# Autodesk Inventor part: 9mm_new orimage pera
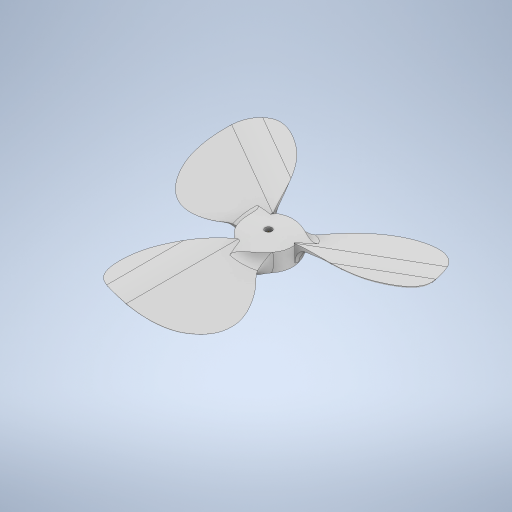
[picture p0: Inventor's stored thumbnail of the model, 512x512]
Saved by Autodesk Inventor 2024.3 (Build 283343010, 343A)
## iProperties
Created: 2025-07
Part Number: 9mm_new orimage pera
Material: 一般
Document SubType Name: Modeling
Designer: node49i5
Density: 1 g/cm^3
Appearance: 既定
Author: node49i5
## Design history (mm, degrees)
sketch "スケッチ1"
  geometry: L1 (-30.949, 12.329)-(37.93, -12.741); L2 (37.93, -12.741)-(37.246, -14.62); L3 (37.246, -14.62)-(-31.302, 10.329); L4 (-37.93, 12.741)-(-37.246, 14.62); L5 (-37.246, 14.62)-(37.246, -14.62); L6 (37.93, -12.741)-(-37.93, 12.741); L7 (-37.246, 14.62)-(36.054, 14.62); L8 (-44.983, 12.741)-(-87.93, 12.741); L9 (-87.93, 12.741)-(-87.93, 14.741); L10 (-87.93, 14.741)-(-44.63, 14.741); L11 (-37.93, 14.741)-(-37.93, 12.741); A1 r 40 centre (-44.63, -25.259) between (-30.949, 12.329) and (-44.63, 14.741); A2 r 40 centre (-44.983, -27.259) between (-31.302, 10.329) and (-44.983, 12.741); 7 further points
  constraints: 22 end point, 8 point on line, 4 parallel, 4 point on circle, 4 tangent, 2 centre point, 2 horizontal, 2 midpoint, 2 perpendicular, 1 equal length, 1 equal radius
  dimensions: "d0" = 80 distance of L4.end L1.end; "d1" = 20 deg angle of L1 L7; "d2" = 2 distance of L1.end L2.end; "d3" = 2 distance of L11.start L4.start; "d4" = 50 distance of L9.end L11.start; "d9" = 40 radius of A1 (derived)
extrude "押し出し1" new body sketch "スケッチ1" distance "d6" = 100; taper "d7" = 0 deg
node "作業平面1"
sketch "スケッチ2"
  geometry: L1 (-37.93, 0)-(30.949, 0) reference; L2 (44.63, 0)-(30.949, 0) reference; L3 (44.63, 0)-(87.93, 0) reference; L4 (30.949, 0)-(30.949, 100) reference; L5 (44.63, 0)-(87.93, 0) reference; L6 (87.93, 0)-(87.93, 100) reference; L7 (44.63, 100)-(87.93, 100) reference; L8 (44.63, 0)-(44.63, 100) reference; L9 (30.949, 0)-(44.63, 0) reference; L10 (44.63, 0)-(44.63, 100) reference; L11 (30.949, 100)-(44.63, 100) reference; L12 (30.949, 0)-(30.949, 100) reference; L13 (-37.93, 0)-(30.949, 0) reference; L14 (30.949, 0)-(30.949, 100) reference; L15 (-37.93, 100)-(30.949, 100) reference; L16 (-37.93, 0)-(-37.93, 100) reference; 38 further points
  constraints: 21 other
  dimensions: "d10" = 9.94761 horizontal distance of point (20.676, 0) point (30.624, -1.041); "d11" = 1.04092 vertical distance of point (20.676, 0) point (30.624, -1.041); "d12" = 0 distance from line of L1 point (20.676, 0); "d45" = 11.68753 distance of point (52.709, 40.854) point (53.63, 52.505); "d46" = 7.46898 distance of point (53.63, 52.505) point (52.49, 59.886); "d47" = 19.54185 distance of point (50.664, 33.189) point (53.63, 52.505); "d48" = 12.36264 distance of point (53.63, 52.505) point (50.15, 64.367); "d49" = 29.23719 distance of point (46.769, 24.084) point (53.63, 52.505); "d50" = 16.67901 distance of point (53.63, 52.505) point (46.053, 67.363); "d51" = 41.60846 distance of point (40.339, 13.076) point (53.63, 52.505); "d52" = 22.43867 distance of point (53.63, 52.505) point (38.766, 69.314); "d53" = 58.27878 distance of point (30.624, -1.041) point (53.63, 52.505); "d54" = 30.32407 distance of point (53.63, 52.505) point (28.314, 69.198); "d55" = 61.98945 distance of point (20.676, 0) point (53.63, 52.505); "d56" = 39.24643 distance of point (53.63, 52.505) point (16.7, 65.789); "d57" = 60.90235 distance of point (53.63, 52.505) point (11.699, 8.336); "d58" = 43.39618 distance of point (53.63, 52.505) point (11.48, 62.827); "d59" = 47.01927 distance of point (53.63, 52.505) point (7.089, 59.19); "d60" = 60.66906 distance of point (53.63, 52.505) point (5.993, 14.936); "d61" = 52.6052 distance of point (53.63, 52.505) point (1.057, 50.678); "d62" = 56.29782 distance of point (53.63, 52.505) point (-1.747, 42.366); "d63" = 58.4343 distance of point (53.63, 52.505) point (-2.076, 34.86); "d64" = 19.03382 distance of point (52.709, 40.854) point (52.49, 59.886); "d65" = 7.93234 distance of point (50.664, 33.189) point (52.709, 40.854); "d66" = 23.65264 distance of point (52.709, 40.854) point (50.15, 64.367); "d67" = 17.79037 distance of point (46.769, 24.084) point (52.709, 40.854); "d68" = 27.33244 distance of point (52.709, 40.854) point (46.053, 67.363); "d69" = 30.40715 distance of point (40.339, 13.076) point (52.709, 40.854); "d70" = 31.69225 distance of point (52.709, 40.854) point (38.766, 69.314); "d71" = 47.35906 distance of point (30.624, -1.041) point (52.709, 40.854); "d72" = 37.39633 distance of point (52.709, 40.854) point (28.314, 69.198); "d73" = 43.79921 distance of point (52.709, 40.854) point (16.7, 65.789); "d74" = 52.33729 distance of point (52.709, 40.854) point (11.699, 8.336); "d75" = 46.71921 distance of point (52.709, 40.854) point (11.48, 62.827); "d76" = 49.16722 distance of point (52.709, 40.854) point (7.089, 59.19); "d77" = 53.42376 distance of point (52.709, 40.854) point (5.993, 14.936); "d78" = 52.57797 distance of point (52.709, 40.854) point (1.057, 50.678); "d79" = 54.78678 distance of point (52.709, 40.854) point (-0.019, 25.974); "d80" = 55.11205 distance of point (52.709, 40.854) point (-2.076, 34.86); "d81" = 62.50751 distance of point (52.49, 59.886) point (-0.019, 25.974); "d82" = 56.99659 distance of point (52.49, 59.886) point (-1.747, 42.366); "d83" = 9 distance from line of L8 point (53.63, 52.505)
extrude "押し出し2" cut sketch "スケッチ2" distance "d14" = 100; taper "d15" = 0 deg
node "作業平面2"
sketch "スケッチ3"
  geometry: L1 (20.676, 0)-(30.949, 0) reference; C1 r 15 at (25.488, -13.196); C2 r 2.15 at (25.488, -13.196); 5 further points
  constraints: 2 centre point, 2 coincident, 2 point on line
  dimensions: "d19" = 30 diameter of C1; "d20" = 4.3 diameter of C2; "d90" = 0 horizontal distance of point (25.488, 0) C1.centre
extrude "押し出し3" join sketch "スケッチ3" distance "d21" = 5.8; taper "d22" = 0 deg; dims "d84" = 5.2, "d85" = 0
node "作業平面3"
pattern_circular "円形状パターン2" dims angle "d28" = 360 deg
node "作業点1"
node "作業平面4"
fillet "フィレット1" dims "d30" = 2.9
sketch "スケッチ4"
  geometry: C1 r 2.15 at (-25.488, 13.196) reference; C2 r 15 at (-25.488, 13.196); C3 r 2.15 at (-25.488, 13.196); 1 further point
  constraints: 2 centre point, 2 coincident
  dimensions: "d31" = 4.3 diameter of C3
extrude "押し出し4" join sketch "スケッチ4" distance "d32" = 11; taper "d33" = 0 deg
fillet "フィレット5" dims "d39" = 9
fillet "フィレット6" dims "d40" = 9
node "作業平面5"
sketch "スケッチ9"
  geometry: L1 (-2.15, 0)-(2.15, 0) reference; L2 (-10.514, 0)-(-6.029, 0) reference; L3 (-4.008, 0)-(-5.717, 0) reference; L4 (-4.008, 0)-(14.922, 0) reference; L5 (14.334, 0)-(14.922, 0) reference; L6 (14.334, 0)-(13.432, 0) reference; L7 (14.522, 0)-(-8.786, 0) reference; L8 (-8.522, 0)-(-8.786, 0) reference; L9 (-8.522, 0)-(-9.424, 0) reference; L10 (-6.029, 0)-(-15, 0) reference; L11 (-15, 0)-(0, 2); L12 (0, 2)-(0, 0); L13 (-6.029, 0)-(-5.717, 0) reference; L14 (13.432, 0)-(14.522, 0) reference; L15 (-9.424, 0)-(-10.514, 0) reference; 11 further points
  constraints: 4 end point, 1 perpendicular, 1 point on line
  dimensions: "d94" = 2 distance of L11.end L12.end
revolve "回転4" sketch "スケッチ9" stored, may be unused: angle "d95" = 90 deg
fillet "フィレット10" dims "d96" = 9
fillet "フィレット11" dims "d97" = 8
sketch "スケッチ10"
  geometry: C1 r 2.15 at (-25.488, -13.196) reference; A1 r 15 centre (-25.488, -13.196) between (-29.206, 1.336) and (-39.552, -7.979) reference; A2 r 15 centre (-25.488, -13.196) between (-11.044, -17.243) and (-13.939, -3.625) reference; A3 r 15 centre (-25.488, -13.196) between (-36.215, -23.681) and (-22.974, -27.984) reference; 4 further points
  constraints: 6 other
extrude "押し出し6" cut sketch "スケッチ10" extent not by distance; stored distance "d98" = 0; taper "d99" = 0 deg
feature "χ耀υ耀ф耀ц耀ш耀ъ耀ь耀ю耀" dims "d0" = 80, "d1" = 20 deg, "d2" = 2, "d3" = 2, "d4" = 50, "d6" = 100, "d7" = 0, "d8" = 39, "d9" = 40 (derived), "d10" = 9.94761, "d11" = 1.04092, "d12" = 0, "d14" = 100, "d15" = 0, "d16" = 6, "d19" = 30, "d20" = 4.3, "d21" = 5.8, "d22" = 0, "d23" = 3, "d27" = 30, "d28" = 360 deg, "d30" = 2.9, "d31" = 4.3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
node "ソリッド1"
node "投影ループ1"
node "投影ループ2"
node "投影ループ3"
node "投影ループ5"
node "投影ループ6"
